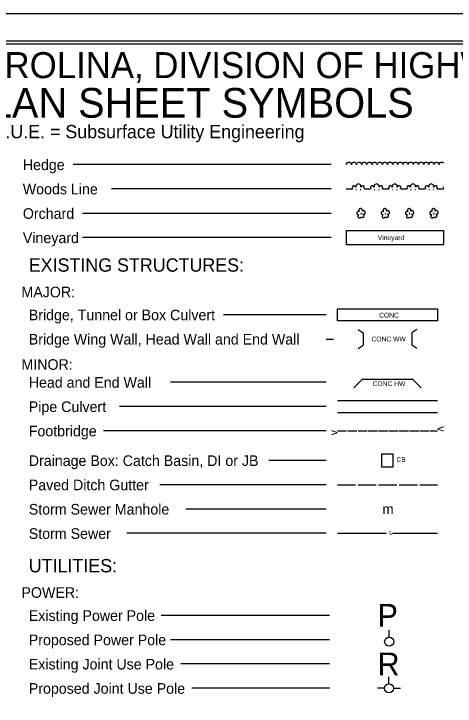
# Model space of a CAD drawing. Extents: x 10000 to 11684, y 10000 to 11100.
# Drawn here: x 10923 to 11286, y 10530 to 11100 of the extents above; entities that cross this region are included whole.
import ezdxf

# ---------------------------------------------------------------- set-up
doc = ezdxf.new("R2010")
doc.units = 0
for name, color, linetype in [('Sheet Cutting Line CELL', 7, 'Continuous'), ('Sheet Plot Border Inside CELL', 7, 'Continuous'), ('Sheet Plot Border Outside CELL', 7, 'Continuous'), ('Sheet Symbology CELL', 7, 'Continuous')]:
    doc.layers.add(name, color=color, linetype=linetype)

msp = doc.modelspace()

# ---------------------------------------------------------------- linework, layer by layer
at = {"layer": 'Sheet Cutting Line CELL'}
msp.add_line((11684, 11100), (10000, 11100), dxfattribs=at)
at = {"layer": 'Sheet Plot Border Inside CELL'}
msp.add_lwpolyline([(10013, 10022.45), (11679.5, 10022.45), (11679.5, 11077.55), (10013, 11077.55)], close=True, dxfattribs=at)
at = {"layer": 'Sheet Plot Border Outside CELL'}
msp.add_lwpolyline([(10000, 10000), (11684, 10000), (11684, 11100), (10000, 11100)], close=True, dxfattribs=at)
at = {"layer": 'Sheet Symbology CELL'}
for p, q in [((11184.28, 10975.85), (10971.59, 10975.85)), ((11196.67, 10975.85), (11196.97, 10976.8)), ((11196.97, 10976.8), (11197.57, 10977.45)), ((11197.57, 10977.45), (11198.37, 10977.9)), ((11198.37, 10977.9), (11199.32, 10977.9)), ((11199.32, 10977.9), (11200.12, 10977.4)), ((11200.12, 10977.4), (11200.67, 10976.75)), ((11200.67, 10976.75), (11200.87, 10975.9)), ((11200.92, 10975.85), (11201.22, 10976.8)), ((11201.22, 10976.8), (11201.82, 10977.45)), ((11201.82, 10977.45), (11202.62, 10977.9)), ((11202.62, 10977.9), (11203.57, 10977.9)), ((11203.57, 10977.9), (11204.37, 10977.4)), ((11204.37, 10977.4), (11204.92, 10976.75)), ((11204.92, 10976.75), (11205.12, 10975.9)), ((11205.17, 10975.85), (11205.47, 10976.8)), ((11205.47, 10976.8), (11206.07, 10977.45)), ((11206.07, 10977.45), (11206.87, 10977.9)), ((11206.87, 10977.9), (11207.82, 10977.9)), ((11207.82, 10977.9), (11208.62, 10977.4)), ((11208.62, 10977.4), (11209.17, 10976.75)), ((11209.17, 10976.75), (11209.37, 10975.9)), ((11209.42, 10975.85), (11209.72, 10976.8)), ((11209.72, 10976.8), (11210.32, 10977.45)), ((11210.32, 10977.45), (11211.12, 10977.9)), ((11211.12, 10977.9), (11212.07, 10977.9)), ((11212.07, 10977.9), (11212.87, 10977.4)), ((11212.87, 10977.4), (11213.42, 10976.75)), ((11213.42, 10976.75), (11213.62, 10975.9)), ((11213.67, 10975.85), (11213.97, 10976.8)), ((11213.97, 10976.8), (11214.57, 10977.45)), ((11214.57, 10977.45), (11215.37, 10977.9)), ((11215.37, 10977.9), (11216.32, 10977.9)), ((11216.32, 10977.9), (11217.12, 10977.4)), ((11217.12, 10977.4), (11217.67, 10976.75)), ((11217.67, 10976.75), (11217.87, 10975.9)), ((11217.92, 10975.85), (11218.22, 10976.8)), ((11218.22, 10976.8), (11218.82, 10977.45)), ((11218.82, 10977.45), (11219.62, 10977.9)), ((11219.62, 10977.9), (11220.57, 10977.9)), ((11220.57, 10977.9), (11221.37, 10977.4)), ((11221.37, 10977.4), (11221.92, 10976.75)), ((11221.92, 10976.75), (11222.12, 10975.9)), ((11222.17, 10975.85), (11222.47, 10976.8)), ((11222.47, 10976.8), (11223.07, 10977.45)), ((11223.07, 10977.45), (11223.87, 10977.9)), ((11223.87, 10977.9), (11224.82, 10977.9)), ((11224.82, 10977.9), (11225.62, 10977.4)), ((11225.62, 10977.4), (11226.17, 10976.75)), ((11226.17, 10976.75), (11226.37, 10975.9)), ((11226.42, 10975.85), (11226.72, 10976.8)), ((11226.72, 10976.8), (11227.32, 10977.45)), ((11227.32, 10977.45), (11228.12, 10977.9)), ((11228.12, 10977.9), (11229.07, 10977.9)), ((11229.07, 10977.9), (11229.87, 10977.4)), ((11229.87, 10977.4), (11230.42, 10976.75)), ((11230.42, 10976.75), (11230.62, 10975.9)), ((11230.67, 10975.85), (11230.97, 10976.8)), ((11230.97, 10976.8), (11231.57, 10977.45)), ((11231.57, 10977.45), (11232.37, 10977.9)), ((11232.37, 10977.9), (11233.32, 10977.9)), ((11233.32, 10977.9), (11234.12, 10977.4)), ((11234.12, 10977.4), (11234.67, 10976.75)), ((11234.67, 10976.75), (11234.87, 10975.9)), ((11234.92, 10975.85), (11235.22, 10976.8)), ((11235.22, 10976.8), (11235.82, 10977.45)), ((11235.82, 10977.45), (11236.62, 10977.9)), ((11236.62, 10977.9), (11237.57, 10977.9)), ((11237.57, 10977.9), (11238.37, 10977.4)), ((11238.37, 10977.4), (11238.92, 10976.75)), ((11238.92, 10976.75), (11239.12, 10975.9)), ((11239.17, 10975.85), (11239.47, 10976.8)), ((11239.47, 10976.8), (11240.07, 10977.45)), ((11240.07, 10977.45), (11240.87, 10977.9)), ((11240.87, 10977.9), (11241.82, 10977.9)), ((11241.82, 10977.9), (11242.62, 10977.4)), ((11242.62, 10977.4), (11243.17, 10976.75)), ((11243.17, 10976.75), (11243.37, 10975.9)), ((11243.42, 10975.85), (11243.72, 10976.8)), ((11243.72, 10976.8), (11244.32, 10977.45)), ((11244.32, 10977.45), (11245.12, 10977.9)), ((11245.12, 10977.9), (11246.07, 10977.9)), ((11246.07, 10977.9), (11246.87, 10977.4)), ((11246.87, 10977.4), (11247.42, 10976.75)), ((11247.42, 10976.75), (11247.62, 10975.9)), ((11247.67, 10975.85), (11247.97, 10976.8)), ((11247.97, 10976.8), (11248.57, 10977.45)), ((11248.57, 10977.45), (11249.37, 10977.9)), ((11249.37, 10977.9), (11250.32, 10977.9)), ((11250.32, 10977.9), (11251.12, 10977.4)), ((11251.12, 10977.4), (11251.67, 10976.75)), ((11251.67, 10976.75), (11251.87, 10975.9)), ((11251.92, 10975.85), (11252.22, 10976.8)), ((11252.22, 10976.8), (11252.82, 10977.45)), ((11252.82, 10977.45), (11253.62, 10977.9)), ((11253.62, 10977.9), (11254.57, 10977.9)), ((11254.57, 10977.9), (11255.37, 10977.4)), ((11255.37, 10977.4), (11255.92, 10976.75)), ((11255.92, 10976.75), (11256.12, 10975.9)), ((11256.17, 10975.85), (11256.47, 10976.8)), ((11256.47, 10976.8), (11257.07, 10977.45)), ((11257.07, 10977.45), (11257.87, 10977.9)), ((11257.87, 10977.9), (11258.82, 10977.9)), ((11258.82, 10977.9), (11259.62, 10977.4)), ((11259.62, 10977.4), (11260.17, 10976.75)), ((11260.17, 10976.75), (11260.37, 10975.9)), ((11260.42, 10975.85), (11260.72, 10976.8)), ((11260.72, 10976.8), (11261.32, 10977.45)), ((11261.32, 10977.45), (11262.12, 10977.9)), ((11262.12, 10977.9), (11263.07, 10977.9)), ((11263.07, 10977.9), (11263.87, 10977.4)), ((11263.87, 10977.4), (11264.42, 10976.75)), ((11264.42, 10976.75), (11264.62, 10975.9)), ((11264.67, 10975.85), (11264.97, 10976.8)), ((11264.97, 10976.8), (11265.57, 10977.45)), ((11265.57, 10977.45), (11266.37, 10977.9)), ((11266.37, 10977.9), (11267.32, 10977.9)), ((11267.32, 10977.9), (11268.12, 10977.4)), ((11268.12, 10977.4), (11268.67, 10976.75)), ((11268.67, 10976.75), (11268.87, 10975.9)), ((11268.92, 10975.85), (11269.22, 10976.8)), ((11269.22, 10976.8), (11269.82, 10977.45)), ((11269.82, 10977.45), (11270.62, 10977.9)), ((11270.62, 10977.9), (11271.57, 10977.9)), ((11271.57, 10977.9), (11272.37, 10977.4)), ((11272.37, 10977.4), (11272.92, 10976.75)), ((11272.92, 10976.75), (11273.12, 10975.9)), ((11273.17, 10975.85), (11273.47, 10976.8)), ((11273.47, 10976.8), (11274.07, 10977.45)), ((11274.07, 10977.45), (11274.87, 10977.9)), ((11274.87, 10977.9), (11275.82, 10977.9)), ((11275.82, 10977.9), (11276.62, 10977.4)), ((11276.62, 10977.4), (11276.67, 10977.35)), ((11184.28, 10955.85), (11003.15, 10955.85)), ((11196.67, 10955.85), (11201.67, 10955.85)), ((11204.62, 10955.35), (11205.12, 10955.35)), ((11208.12, 10955.35), (11208.62, 10955.35)), ((11211.67, 10955.85), (11216.67, 10955.85)), ((11219.62, 10955.35), (11220.12, 10955.35)), ((11223.12, 10955.35), (11223.62, 10955.35)), ((11226.67, 10955.85), (11231.67, 10955.85)), ((11234.62, 10955.35), (11235.12, 10955.35)), ((11238.12, 10955.35), (11238.62, 10955.35)), ((11241.67, 10955.85), (11246.67, 10955.85)), ((11249.62, 10955.35), (11250.12, 10955.35)), ((11253.12, 10955.35), (11253.62, 10955.35)), ((11256.67, 10955.85), (11261.67, 10955.85)), ((11264.62, 10955.35), (11265.12, 10955.35)), ((11268.12, 10955.35), (11268.62, 10955.35)), ((11271.67, 10955.85), (11276.67, 10955.85)), ((11184.33, 10935.72), (10979.39, 10935.72)), ((11184.33, 10915.72), (10979.39, 10915.72)), ((11180.01, 10852.21), (11095.59, 10852.21)), ((11206.46, 10840.07), (11210.56, 10837.21)), ((11254.66, 10840.07), (11250.56, 10837.21)), ((11180.01, 10832.21), (11186, 10832.21)), ((11210.56, 10837.21), (11210.56, 10827.21)), ((11250.56, 10837.21), (11250.56, 10827.21)), ((11206.46, 10824.35), (11210.56, 10827.21)), ((11254.66, 10824.35), (11250.56, 10827.21)), ((11202.86, 10792.06), (11209.94, 10799.14)), ((11209.94, 10799.14), (11251.19, 10799.14)), ((11251.19, 10799.14), (11258.26, 10792.06)), ((11180.01, 10796.64), (11051.71, 10796.64)), ((11189.31, 10781.64), (11271.81, 10781.64)), ((11180.01, 10776.64), (11009.83, 10776.64)), ((11189.31, 10771.64), (11271.81, 10771.64)), ((11180.01, 10756.64), (10996.54, 10756.64)), ((11189.31, 10756.64), (11196.81, 10756.64)), ((11197.81, 10756.64), (11205.31, 10756.64)), ((11206.31, 10756.64), (11213.81, 10756.64)), ((11214.81, 10756.64), (11222.31, 10756.64)), ((11223.31, 10756.64), (11230.81, 10756.64)), ((11231.81, 10756.64), (11239.31, 10756.64)), ((11240.31, 10756.64), (11247.81, 10756.64)), ((11248.81, 10756.64), (11256.31, 10756.64)), ((11257.31, 10756.64), (11264.81, 10756.64)), ((11265.81, 10756.64), (11271.81, 10756.64)), ((11180.01, 10732.21), (11132.81, 10732.21)), ((11180.01, 10712.21), (11043.06, 10712.21)), ((11189.31, 10712.21), (11204.31, 10712.21)), ((11206.31, 10712.21), (11221.31, 10712.21)), ((11223.31, 10712.21), (11238.31, 10712.21)), ((11240.31, 10712.21), (11255.31, 10712.21)), ((11257.31, 10712.21), (11271.81, 10712.21)), ((11180.01, 10692.21), (11064.34, 10692.21)), ((11180.01, 10672.21), (11015.81, 10672.21)), ((11189.31, 10672.21), (11229.84, 10672.21)), ((11234.84, 10672.21), (11271.81, 10672.21)), ((11182.8, 10604.62), (11044.1, 10604.62)), ((11232.02, 10586.73), (11232.02, 10592.36)), ((11182.8, 10584.62), (11051.89, 10584.62)), ((11182.8, 10564.62), (11060.29, 10564.62)), ((11231.81, 10548.38), (11231.81, 10554.01)), ((11182.8, 10544.62), (11069.29, 10544.62)), ((11228.06, 10544.63), (11222.44, 10544.63)), ((11235.56, 10544.63), (11241.19, 10544.63))]:
    msp.add_line(p, q, dxfattribs=at)
for points in [[(11667, 11075), (10167, 11075), (10167, 10026.02), (11667, 10026.02)], [(11225.75, 10726.9), (11235.36, 10726.9), (11235.36, 10737.53), (11225.75, 10737.53)]]:
    msp.add_lwpolyline(points, close=True, dxfattribs=at)
for points in [[(11209.77, 10937.47), (11209.92, 10937.77), (11209.97, 10938.07), (11209.92, 10938.37), (11209.87, 10938.67), (11209.72, 10938.92), (11209.57, 10939.17), (11209.32, 10939.37), (11209.07, 10939.52), (11208.72, 10939.62), (11208.47, 10939.62), (11208.17, 10939.57), (11207.87, 10939.47), (11207.62, 10939.32), (11207.37, 10939.12), (11207.22, 10938.82), (11207.12, 10938.57), (11207.07, 10938.27), (11207.07, 10937.97), (11207.12, 10937.67), (11207.27, 10937.42), (11207.47, 10937.12), (11207.22, 10937.27), (11206.92, 10937.32), (11206.62, 10937.32), (11206.37, 10937.22), (11206.12, 10937.12), (11205.87, 10936.92), (11205.67, 10936.72), (11205.52, 10936.47), (11205.47, 10936.22), (11205.42, 10935.87), (11205.47, 10935.62), (11205.57, 10935.37), (11205.77, 10935.12), (11205.92, 10934.92), (11206.17, 10934.77), (11206.47, 10934.62), (11206.72, 10934.57), (11207.02, 10934.57), (11206.77, 10934.47), (11206.52, 10934.27), (11206.37, 10934.07), (11206.27, 10933.77), (11206.17, 10933.47), (11206.17, 10933.22), (11206.22, 10932.92), (11206.37, 10932.67), (11206.52, 10932.42), (11206.72, 10932.22), (11206.97, 10932.07), (11207.22, 10931.97), (11207.52, 10931.97), (11207.82, 10931.97), (11208.07, 10932.02), (11208.32, 10932.22), (11208.57, 10932.37), (11208.82, 10932.82)], [(11208.92, 10935.72), (11208.77, 10935.72), (11208.67, 10935.67), (11208.57, 10935.62), (11208.57, 10935.47), (11208.57, 10935.37), (11208.67, 10935.27), (11208.82, 10935.27), (11208.92, 10935.27), (11209.02, 10935.37), (11209.07, 10935.52), (11209.02, 10935.62), (11208.92, 10935.72)], [(11208.82, 10932.82), (11209.42, 10932.47), (11209.72, 10932.37), (11210.02, 10932.32), (11210.32, 10932.37), (11210.57, 10932.47), (11210.82, 10932.62), (11211.07, 10932.82), (11211.22, 10933.07), (11211.32, 10933.32), (11211.42, 10933.62), (11211.37, 10933.92), (11211.32, 10934.22), (11211.12, 10934.52), (11210.97, 10934.72), (11210.72, 10934.87), (11210.42, 10935.02), (11210.72, 10934.97), (11211.07, 10934.97), (11211.32, 10935.07), (11211.62, 10935.22), (11211.87, 10935.37), (11212.07, 10935.62), (11212.22, 10935.92), (11212.27, 10936.22), (11212.32, 10936.52), (11212.27, 10936.82), (11212.17, 10937.12), (11211.97, 10937.37), (11211.72, 10937.62), (11211.47, 10937.77), (11211.17, 10937.87), (11210.87, 10937.92), (11210.57, 10937.92), (11210.27, 10937.82), (11210.02, 10937.67), (11209.77, 10937.47)], [(11229.77, 10937.47), (11229.92, 10937.77), (11229.97, 10938.07), (11229.92, 10938.37), (11229.87, 10938.67), (11229.72, 10938.92), (11229.57, 10939.17), (11229.32, 10939.37), (11229.07, 10939.52), (11228.72, 10939.62), (11228.47, 10939.62), (11228.17, 10939.57), (11227.87, 10939.47), (11227.62, 10939.32), (11227.37, 10939.12), (11227.22, 10938.82), (11227.12, 10938.57), (11227.07, 10938.27), (11227.07, 10937.97), (11227.12, 10937.67), (11227.27, 10937.42), (11227.47, 10937.12), (11227.22, 10937.27), (11226.92, 10937.32), (11226.62, 10937.32), (11226.37, 10937.22), (11226.12, 10937.12), (11225.87, 10936.92), (11225.67, 10936.72), (11225.52, 10936.47), (11225.47, 10936.22), (11225.42, 10935.87), (11225.47, 10935.62), (11225.57, 10935.37), (11225.77, 10935.12), (11225.92, 10934.92), (11226.17, 10934.77), (11226.47, 10934.62), (11226.72, 10934.57), (11227.02, 10934.57), (11226.77, 10934.47), (11226.52, 10934.27), (11226.37, 10934.07), (11226.27, 10933.77), (11226.17, 10933.47), (11226.17, 10933.22), (11226.22, 10932.92), (11226.37, 10932.67), (11226.52, 10932.42), (11226.72, 10932.22), (11226.97, 10932.07), (11227.22, 10931.97), (11227.52, 10931.97), (11227.82, 10931.97), (11228.07, 10932.02), (11228.32, 10932.22), (11228.57, 10932.37), (11228.82, 10932.82)], [(11228.92, 10935.72), (11228.77, 10935.72), (11228.67, 10935.67), (11228.57, 10935.62), (11228.57, 10935.47), (11228.57, 10935.37), (11228.67, 10935.27), (11228.82, 10935.27), (11228.92, 10935.27), (11229.02, 10935.37), (11229.07, 10935.52), (11229.02, 10935.62), (11228.92, 10935.72)], [(11228.82, 10932.82), (11229.42, 10932.47), (11229.72, 10932.37), (11230.02, 10932.32), (11230.32, 10932.37), (11230.57, 10932.47), (11230.82, 10932.62), (11231.07, 10932.82), (11231.22, 10933.07), (11231.32, 10933.32), (11231.42, 10933.62), (11231.37, 10933.92), (11231.32, 10934.22), (11231.12, 10934.52), (11230.97, 10934.72), (11230.72, 10934.87), (11230.42, 10935.02), (11230.72, 10934.97), (11231.07, 10934.97), (11231.32, 10935.07), (11231.62, 10935.22), (11231.87, 10935.37), (11232.07, 10935.62), (11232.22, 10935.92), (11232.27, 10936.22), (11232.32, 10936.52), (11232.27, 10936.82), (11232.17, 10937.12), (11231.97, 10937.37), (11231.72, 10937.62), (11231.47, 10937.77), (11231.17, 10937.87), (11230.87, 10937.92), (11230.57, 10937.92), (11230.27, 10937.82), (11230.02, 10937.67), (11229.77, 10937.47)], [(11249.77, 10937.47), (11249.92, 10937.77), (11249.97, 10938.07), (11249.92, 10938.37), (11249.87, 10938.67), (11249.72, 10938.92), (11249.57, 10939.17), (11249.32, 10939.37), (11249.07, 10939.52), (11248.72, 10939.62), (11248.47, 10939.62), (11248.17, 10939.57), (11247.87, 10939.47), (11247.62, 10939.32), (11247.37, 10939.12), (11247.22, 10938.82), (11247.12, 10938.57), (11247.07, 10938.27), (11247.07, 10937.97), (11247.12, 10937.67), (11247.27, 10937.42), (11247.47, 10937.12), (11247.22, 10937.27), (11246.92, 10937.32), (11246.62, 10937.32), (11246.37, 10937.22), (11246.12, 10937.12), (11245.87, 10936.92), (11245.67, 10936.72), (11245.52, 10936.47), (11245.47, 10936.22), (11245.42, 10935.87), (11245.47, 10935.62), (11245.57, 10935.37), (11245.77, 10935.12), (11245.92, 10934.92), (11246.17, 10934.77), (11246.47, 10934.62), (11246.72, 10934.57), (11247.02, 10934.57), (11246.77, 10934.47), (11246.52, 10934.27), (11246.37, 10934.07), (11246.27, 10933.77), (11246.17, 10933.47), (11246.17, 10933.22), (11246.22, 10932.92), (11246.37, 10932.67), (11246.52, 10932.42), (11246.72, 10932.22), (11246.97, 10932.07), (11247.22, 10931.97), (11247.52, 10931.97), (11247.82, 10931.97), (11248.07, 10932.02), (11248.32, 10932.22), (11248.57, 10932.37), (11248.82, 10932.82)], [(11248.92, 10935.72), (11248.77, 10935.72), (11248.67, 10935.67), (11248.57, 10935.62), (11248.57, 10935.47), (11248.57, 10935.37), (11248.67, 10935.27), (11248.82, 10935.27), (11248.92, 10935.27), (11249.02, 10935.37), (11249.07, 10935.52), (11249.02, 10935.62), (11248.92, 10935.72)], [(11248.82, 10932.82), (11249.42, 10932.47), (11249.72, 10932.37), (11250.02, 10932.32), (11250.32, 10932.37), (11250.57, 10932.47), (11250.82, 10932.62), (11251.07, 10932.82), (11251.22, 10933.07), (11251.32, 10933.32), (11251.42, 10933.62), (11251.37, 10933.92), (11251.32, 10934.22), (11251.12, 10934.52), (11250.97, 10934.72), (11250.72, 10934.87), (11250.42, 10935.02), (11250.72, 10934.97), (11251.07, 10934.97), (11251.32, 10935.07), (11251.62, 10935.22), (11251.87, 10935.37), (11252.07, 10935.62), (11252.22, 10935.92), (11252.27, 10936.22), (11252.32, 10936.52), (11252.27, 10936.82), (11252.17, 10937.12), (11251.97, 10937.37), (11251.72, 10937.62), (11251.47, 10937.77), (11251.17, 10937.87), (11250.87, 10937.92), (11250.57, 10937.92), (11250.27, 10937.82), (11250.02, 10937.67), (11249.77, 10937.47)], [(11269.77, 10937.47), (11269.92, 10937.77), (11269.97, 10938.07), (11269.92, 10938.37), (11269.87, 10938.67), (11269.72, 10938.92), (11269.57, 10939.17), (11269.32, 10939.37), (11269.07, 10939.52), (11268.72, 10939.62), (11268.47, 10939.62), (11268.17, 10939.57), (11267.87, 10939.47), (11267.62, 10939.32), (11267.37, 10939.12), (11267.22, 10938.82), (11267.12, 10938.57), (11267.07, 10938.27), (11267.07, 10937.97), (11267.12, 10937.67), (11267.27, 10937.42), (11267.47, 10937.12), (11267.22, 10937.27), (11266.92, 10937.32), (11266.62, 10937.32), (11266.37, 10937.22), (11266.12, 10937.12), (11265.87, 10936.92), (11265.67, 10936.72), (11265.52, 10936.47), (11265.47, 10936.22), (11265.42, 10935.87), (11265.47, 10935.62), (11265.57, 10935.37), (11265.77, 10935.12), (11265.92, 10934.92), (11266.17, 10934.77), (11266.47, 10934.62), (11266.72, 10934.57), (11267.02, 10934.57), (11266.77, 10934.47), (11266.52, 10934.27), (11266.37, 10934.07), (11266.27, 10933.77), (11266.17, 10933.47), (11266.17, 10933.22), (11266.22, 10932.92), (11266.37, 10932.67), (11266.52, 10932.42), (11266.72, 10932.22), (11266.97, 10932.07), (11267.22, 10931.97), (11267.52, 10931.97), (11267.82, 10931.97), (11268.07, 10932.02), (11268.32, 10932.22), (11268.57, 10932.37), (11268.82, 10932.82)], [(11268.92, 10935.72), (11268.77, 10935.72), (11268.67, 10935.67), (11268.57, 10935.62), (11268.57, 10935.47), (11268.57, 10935.37), (11268.67, 10935.27), (11268.82, 10935.27), (11268.92, 10935.27), (11269.02, 10935.37), (11269.07, 10935.52), (11269.02, 10935.62), (11268.92, 10935.72)], [(11268.82, 10932.82), (11269.42, 10932.47), (11269.72, 10932.37), (11270.02, 10932.32), (11270.32, 10932.37), (11270.57, 10932.47), (11270.82, 10932.62), (11271.07, 10932.82), (11271.22, 10933.07), (11271.32, 10933.32), (11271.42, 10933.62), (11271.37, 10933.92), (11271.32, 10934.22), (11271.12, 10934.52), (11270.97, 10934.72), (11270.72, 10934.87), (11270.42, 10935.02), (11270.72, 10934.97), (11271.07, 10934.97), (11271.32, 10935.07), (11271.62, 10935.22), (11271.87, 10935.37), (11272.07, 10935.62), (11272.22, 10935.92), (11272.27, 10936.22), (11272.32, 10936.52), (11272.27, 10936.82), (11272.17, 10937.12), (11271.97, 10937.37), (11271.72, 10937.62), (11271.47, 10937.77), (11271.17, 10937.87), (11270.87, 10937.92), (11270.57, 10937.92), (11270.27, 10937.82), (11270.02, 10937.67), (11269.77, 10937.47)], [(11196.72, 10921.72), (11276.72, 10921.72), (11276.72, 10909.72), (11196.72, 10909.72), (11196.72, 10921.72)], [(11189.31, 10857.21), (11271.81, 10857.21), (11271.81, 10847.21), (11189.31, 10847.21), (11189.31, 10857.21)]]:
    msp.add_lwpolyline(points, dxfattribs=at)
for centre in [(11232.02, 10582.98), (11231.81, 10544.62)]:
    msp.add_circle(centre, 3.75, dxfattribs=at)
for centre, radius, start, end in [((11203.12, 10956.87), 1.58, 18.435, 219.2315), ((11206.62, 10957.87), 2.06, 345.9638, 194.0362), ((11210.12, 10956.87), 1.58, 320.7685, 161.5651), ((11218.12, 10956.87), 1.58, 18.435, 219.2315), ((11221.62, 10957.87), 2.06, 345.9638, 194.0362), ((11225.12, 10956.87), 1.58, 320.7685, 161.5651), ((11233.12, 10956.87), 1.58, 18.435, 219.2315), ((11236.62, 10957.87), 2.06, 345.9638, 194.0362), ((11240.12, 10956.87), 1.58, 320.7685, 161.5651), ((11248.12, 10956.87), 1.58, 18.435, 219.2315), ((11251.62, 10957.87), 2.06, 345.9638, 194.0362), ((11255.12, 10956.87), 1.58, 320.7685, 161.5651), ((11263.12, 10956.87), 1.58, 18.435, 219.2315), ((11266.62, 10957.87), 2.06, 345.9638, 194.0362), ((11270.12, 10956.87), 1.58, 320.7685, 161.5651), ((11278.12, 10956.87), 1.58, 156.251, 203.749)]:
    msp.add_arc(centre, radius, start, end, dxfattribs=at)

# ---------------------------------------------------------------- texts
for s, height, p in [('STATE OF NORTH CAROLINA, DIVISION OF HIGHWAYS', 21.419, (10617.56, 11047.04)), ('CONVENTIONAL  PLAN SHEET SYMBOLS', 24.4803, (10604.61, 11014.47)), ('Hedge', 8.75, (10930.12, 10971.33)), ('Woods Line', 8.75, (10930.12, 10951.33)), ('Orchard', 8.75, (10930.17, 10931.19)), ('Vineyard', 8.75, (10930.17, 10911.19)), ('EXISTING STRUCTURES:', 11, (10935.05, 10887.66)), ('MAJOR:', 8.75, (10929.02, 10866.55)), ('Bridge, Tunnel or Box Culvert', 8.75, (10935.05, 10847.66)), ('CONC', 4, (11223.75, 10849.85)), ('Bridge Wing Wall, Head Wall and End Wall', 8.75, (10935.05, 10827.66)), ('MINOR:', 8.75, (10929.02, 10806.85)), ('Head and End Wall', 8.75, (10935.05, 10792.09)), ('Pipe Culvert', 8.75, (10935.05, 10772.1)), ('Footbridge', 8.75, (10935.06, 10752.1)), ('Drainage Box: Catch Basin, DI or JB', 8.75, (10935.06, 10727.67)), ('Paved Ditch Gutter', 8.75, (10935.06, 10707.66)), ('Storm Sewer Manhole', 8.75, (10935.06, 10687.66)), ('m', 8.25, (11226.44, 10688.08)), ('Storm Sewer', 8.75, (10935.06, 10667.66)), ('S', 3, (11231.44, 10670.71)), ('UTILITIES:', 11, (10935.05, 10640.07)), ('POWER:', 8.75, (10929.02, 10619.08)), ('P', 18.75, (11222.44, 10595.25)), ('Existing Power Pole', 8.75, (10935.06, 10600.08)), ('Proposed Power Pole', 8.75, (10935.06, 10580.08)), ('R', 18.75, (11222.44, 10555.25)), ('Existing Joint Use Pole', 8.75, (10935.06, 10560.1)), ('Proposed Joint Use Pole', 8.75, (10935.08, 10540.08))]:
    msp.add_text(s, height=height, dxfattribs=at).set_placement(p)
for s, height, rotation, p in [('*S.U.E. = Subsurface Utility Engineering', 11, 360, (10900.22, 10997.51)), ('Vineyard', 4, 0, (11222.55, 10913.72)), ('CONC WW', 4, 0, (11217.44, 10830.21)), ('CONC HW', 4, 360, (11218.36, 10793.48)), ('v', 6.6, 270.2409, (11271.8, 10760.38)), ('v', 6.6, 89.7591, (11189.3, 10752.9)), ('CB', 4, 360, (11238, 10731.03))]:
    msp.add_text(s, height=height, rotation=rotation, dxfattribs=at).set_placement(p)

doc.saveas('drawing.dxf')
